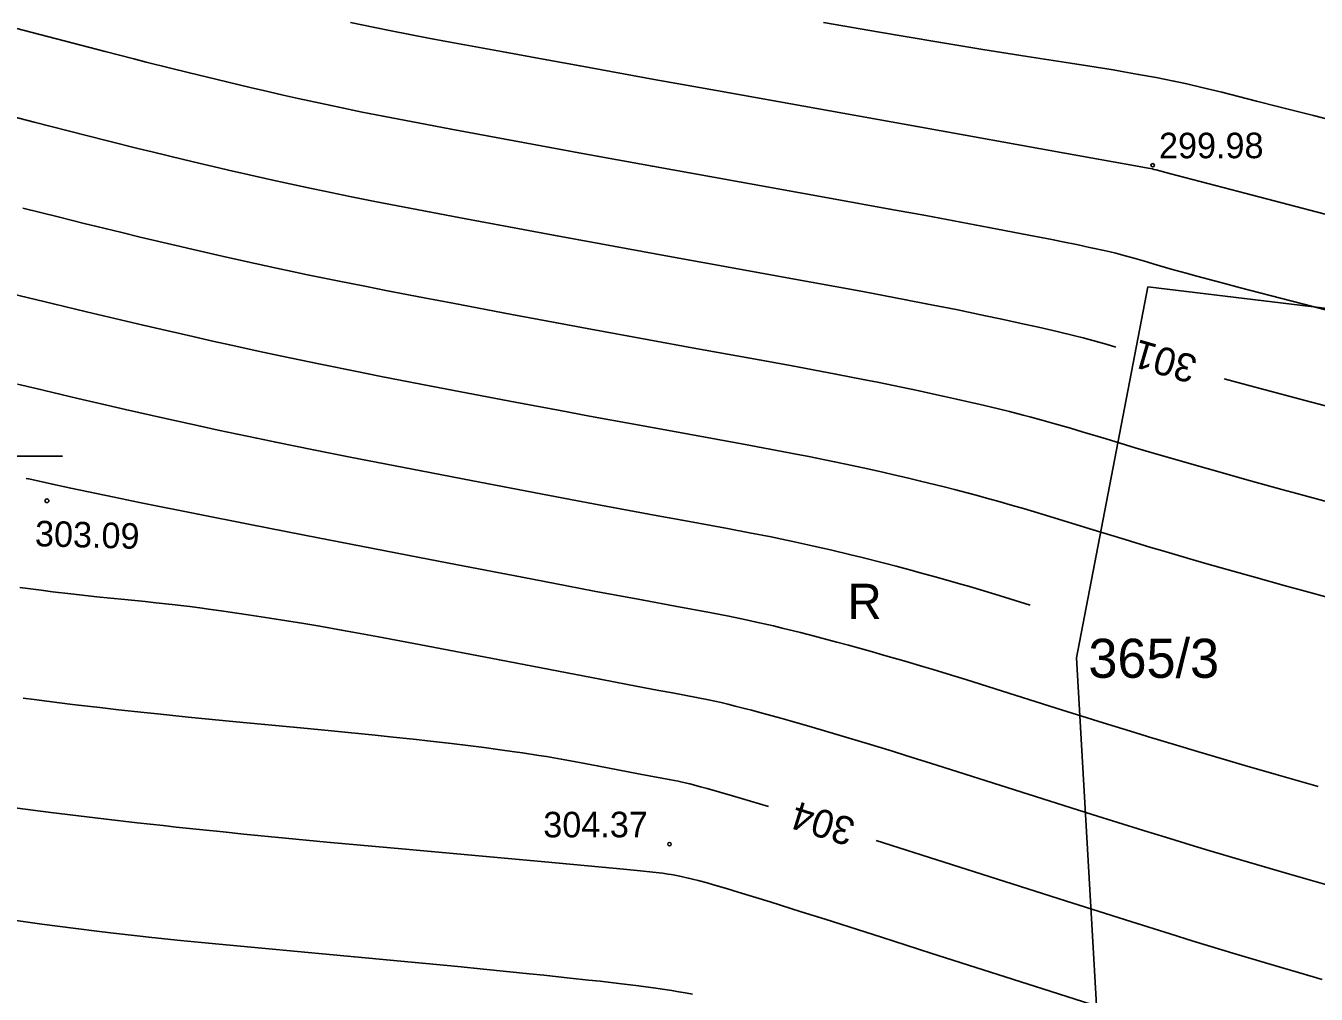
# Model space of a CAD drawing. Extents: x 7477803 to 7478145, y 5500698 to 5500984.
# Drawn here: x 7477901.52 to 7477935.87, y 5500835.67 to 5500861.45 of the extents above; entities that cross this region are included whole.
import ezdxf

# ---------------------------------------------------------------- set-up
doc = ezdxf.new("R2010")
doc.units = 0
for name, color, linetype in [('nr_dzialki', 7, 'Continuous'), ('opis_uzytek', 7, 'Continuous'), ('pkt_wys', 7, 'Continuous'), ('robocza49', 7, 'Continuous'), ('uwagi_projektanci', 7, 'Continuous'), ('warst_ciagla', 7, 'Continuous'), ('warst_opis', 7, 'Continuous'), ('warst_pogrub', 7, 'Continuous'), ('warst_przeryw', 7, 'Continuous')]:
    doc.layers.add(name, color=color, linetype=linetype)

# ---------------------------------------------------------------- blocks, each defined once
blk = doc.blocks.new('801_3')
at = {"layer": 'pkt_wys'}
blk.add_circle((0, 0), 0.045, dxfattribs=at)
blk.add_circle((0, 0), 0.045, dxfattribs=at)
blk = doc.blocks.new('801_5')
at = {"layer": 'pkt_wys'}
blk.add_circle((0, 0), 0.05, dxfattribs=at)
blk.add_circle((0, 0), 0.05, dxfattribs=at)

msp = doc.modelspace()

# ---------------------------------------------------------------- linework, layer by layer
at = {"layer": 'robocza49'}
msp.add_line((7477897.5, 5500850), (7477902.5, 5500850), dxfattribs=at)
at = {"layer": 'uwagi_projektanci'}
msp.add_lwpolyline([(7477973.16, 5500821.11), (7477976.42, 5500829.04), (7477976.7, 5500837.68), (7477975.34, 5500846.14), (7477969.75, 5500849.6), (7477966.4, 5500846.83), (7477944.18, 5500852.96), (7477931.39, 5500854.5), (7477929.49, 5500844.63), (7477930.21, 5500832.13), (7477946.85, 5500819.35), (7477963.16, 5500817.62)], close=True, dxfattribs=at)
at = {"layer": 'warst_ciagla'}
for points in [[(7477900.789, 5500859.139), (7477901.747, 5500858.889), (7477903.136, 5500858.533), (7477903.733, 5500858.383), (7477904.509, 5500858.19), (7477904.889, 5500858.096), (7477905.724, 5500857.895), (7477906.13, 5500857.798), (7477906.662, 5500857.673), (7477906.923, 5500857.612), (7477907.436, 5500857.495), (7477908.1, 5500857.345), (7477908.424, 5500857.274), (7477909.132, 5500857.121), (7477909.476, 5500857.049), (7477910.149, 5500856.911), (7477910.813, 5500856.778), (7477912.162, 5500856.517), (7477913.235, 5500856.314), (7477914.764, 5500856.028), (7477915.57, 5500855.878), (7477916.832, 5500855.646), (7477918.612, 5500855.321), (7477919.544, 5500855.152), (7477922.426, 5500854.631), (7477923.808, 5500854.377), (7477924.95, 5500854.16), (7477925.494, 5500854.055), (7477926.288, 5500853.896), (7477927.068, 5500853.735), (7477927.456, 5500853.653), (7477928.145, 5500853.503), (7477928.484, 5500853.427), (7477928.979, 5500853.313), (7477929.449, 5500853.198), (7477929.672, 5500853.142), (7477930.088, 5500853.03), (7477930.279, 5500852.975), (7477930.54, 5500852.895)], [(7477936.319, 5500846.197), (7477935.483, 5500846.426), (7477935.078, 5500846.537), (7477934.199, 5500846.782), (7477932.962, 5500847.132), (7477932.445, 5500847.282), (7477931.785, 5500847.475), (7477931.468, 5500847.568), (7477930.787, 5500847.773), (7477929.842, 5500848.064), (7477928.664, 5500848.427), (7477928.082, 5500848.6), (7477927.789, 5500848.686), (7477927.393, 5500848.798), (7477927.193, 5500848.853), (7477926.789, 5500848.962), (7477926.244, 5500849.105), (7477925.968, 5500849.176), (7477925.339, 5500849.331), (7477925.02, 5500849.408), (7477924.591, 5500849.508), (7477924.374, 5500849.557), (7477923.938, 5500849.655), (7477923.348, 5500849.782), (7477923.05, 5500849.845), (7477922.371, 5500849.983), (7477922.027, 5500850.05), (7477921.331, 5500850.183), (7477920.624, 5500850.314), (7477919.176, 5500850.578), (7477918.059, 5500850.782), (7477916.53, 5500851.065), (7477915.748, 5500851.211), (7477914.553, 5500851.436), (7477912.919, 5500851.747), (7477912.085, 5500851.907), (7477910.942, 5500852.129), (7477910.34, 5500852.248), (7477909.371, 5500852.444), (7477908.295, 5500852.668), (7477907.707, 5500852.794), (7477906.953, 5500852.958), (7477906.54, 5500853.05), (7477905.856, 5500853.204), (7477904.644, 5500853.483), (7477903.142, 5500853.837), (7477902.26, 5500854.048), (7477900.187, 5500854.55)], [(7477933.421, 5500852.058), (7477934.247, 5500851.836), (7477935.745, 5500851.437), (7477937.058, 5500851.091)], [(7477935.921, 5500841.204), (7477935.177, 5500841.414), (7477934.805, 5500841.52), (7477933.968, 5500841.762), (7477932.713, 5500842.131), (7477932.155, 5500842.298), (7477931.411, 5500842.523), (7477931.04, 5500842.637), (7477930.203, 5500842.896), (7477928.952, 5500843.289), (7477927.324, 5500843.803), (7477926.544, 5500844.046), (7477926.165, 5500844.163), (7477925.672, 5500844.313), (7477925.431, 5500844.385), (7477924.959, 5500844.525), (7477924.352, 5500844.702), (7477924.058, 5500844.786), (7477923.418, 5500844.964), (7477923.11, 5500845.048), (7477922.712, 5500845.155), (7477922.519, 5500845.205), (7477922.142, 5500845.302), (7477921.661, 5500845.42), (7477921.43, 5500845.475), (7477920.933, 5500845.589), (7477920.695, 5500845.64), (7477920.236, 5500845.735), (7477919.78, 5500845.823), (7477918.807, 5500846.003), (7477917.962, 5500846.16), (7477916.656, 5500846.406), (7477915.926, 5500846.545), (7477914.735, 5500846.772), (7477912.968, 5500847.112), (7477912.008, 5500847.297), (7477908.94, 5500847.893), (7477907.456, 5500848.184), (7477906.11, 5500848.451), (7477904.554, 5500848.763), (7477903.877, 5500848.901), (7477902.722, 5500849.141), (7477902.234, 5500849.246), (7477901.603, 5500849.388), (7477901.531, 5500849.405)], [(7477901.457, 5500843.553), (7477901.746, 5500843.515), (7477902.421, 5500843.43), (7477902.77, 5500843.387), (7477903.248, 5500843.331), (7477903.492, 5500843.303), (7477903.991, 5500843.247), (7477904.678, 5500843.172), (7477905.031, 5500843.135), (7477905.847, 5500843.051), (7477907.122, 5500842.927), (7477908.835, 5500842.764), (7477909.66, 5500842.685), (7477910.822, 5500842.568), (7477911.307, 5500842.517), (7477911.925, 5500842.45), (7477912.221, 5500842.417), (7477912.856, 5500842.343), (7477913.728, 5500842.236), (7477914.085, 5500842.189), (7477914.531, 5500842.128), (7477914.741, 5500842.097), (7477915.183, 5500842.031), (7477915.388, 5500841.998), (7477915.77, 5500841.933), (7477916.117, 5500841.87), (7477916.734, 5500841.753), (7477917.873, 5500841.534), (7477918.692, 5500841.38), (7477918.885, 5500841.343), (7477918.994, 5500841.319), (7477919.199, 5500841.27), (7477919.482, 5500841.195), (7477919.661, 5500841.145), (7477920.334, 5500840.952), (7477921.296, 5500840.667)], [(7477924.157, 5500839.765), (7477929.2, 5500838.154), (7477930.967, 5500837.596), (7477931.98, 5500837.28), (7477932.599, 5500837.088), (7477933.738, 5500836.741), (7477934.912, 5500836.39), (7477935.403, 5500836.246), (7477936.026, 5500836.065)]]:
    msp.add_lwpolyline(points, dxfattribs=at)
at = {"layer": 'warst_pogrub'}
for points in [[(7477937.398, 5500856.105), (7477933.804, 5500857.043), (7477931.971, 5500857.521), (7477931.609, 5500857.616), (7477931.553, 5500857.631), (7477931.512, 5500857.642), (7477931.397, 5500857.665), (7477931.159, 5500857.709), (7477929.18, 5500858.065), (7477925.246, 5500858.77), (7477919.912, 5500859.727), (7477918.254, 5500860.025), (7477916.278, 5500860.383), (7477915.392, 5500860.545), (7477914.189, 5500860.765), (7477912.822, 5500861.018), (7477912.239, 5500861.127), (7477911.252, 5500861.316), (7477910.812, 5500861.404), (7477910.167, 5500861.537)], [(7477919.267, 5500835.671), (7477919.132, 5500835.697), (7477918.849, 5500835.748), (7477918.718, 5500835.771), (7477918.469, 5500835.81), (7477918.233, 5500835.844), (7477917.762, 5500835.905), (7477917.378, 5500835.95), (7477916.811, 5500836.015), (7477916.504, 5500836.049), (7477916.015, 5500836.102), (7477915.309, 5500836.177), (7477914.933, 5500836.215), (7477913.704, 5500836.339), (7477913.022, 5500836.406), (7477910.655, 5500836.633), (7477907.807, 5500836.898), (7477906.387, 5500837.03), (7477905.644, 5500837.103), (7477904.88, 5500837.182), (7477904.49, 5500837.224), (7477903.783, 5500837.305), (7477903.419, 5500837.349), (7477902.853, 5500837.42), (7477901.949, 5500837.54), (7477900.957, 5500837.679)]]:
    msp.add_lwpolyline(points, dxfattribs=at)
at = {"layer": 'warst_przeryw'}
for points in [[(7477938.209, 5500853.343), (7477935.746, 5500853.985), (7477933.859, 5500854.477), (7477933.331, 5500854.618), (7477932.696, 5500854.789), (7477932.409, 5500854.868), (7477932.014, 5500854.978), (7477931.557, 5500855.109), (7477931.359, 5500855.168), (7477930.993, 5500855.276), (7477930.787, 5500855.333), (7477930.538, 5500855.397), (7477930.39, 5500855.432), (7477930.224, 5500855.47), (7477929.973, 5500855.525), (7477929.836, 5500855.555), (7477929.535, 5500855.618), (7477929.082, 5500855.711), (7477928.834, 5500855.761), (7477928.22, 5500855.882), (7477927.158, 5500856.086), (7477925.48, 5500856.399), (7477924.527, 5500856.573), (7477922.974, 5500856.855), (7477919.728, 5500857.439), (7477918.205, 5500857.715), (7477916.341, 5500858.054), (7477915.481, 5500858.211), (7477914.28, 5500858.433), (7477912.846, 5500858.7), (7477912.201, 5500858.822), (7477911.033, 5500859.047), (7477910.481, 5500859.157), (7477909.65, 5500859.329), (7477908.776, 5500859.519), (7477908.371, 5500859.61), (7477907.816, 5500859.737), (7477907.531, 5500859.803), (7477906.875, 5500859.959), (7477905.847, 5500860.209), (7477905.374, 5500860.326), (7477904.727, 5500860.489), (7477904.397, 5500860.573), (7477903.638, 5500860.768), (7477901.247, 5500861.391)], [(7477922.756, 5500861.544), (7477924.244, 5500861.285), (7477924.927, 5500861.168), (7477925.876, 5500861.008), (7477927, 5500860.822), (7477927.501, 5500860.742), (7477928.18, 5500860.635), (7477929.334, 5500860.457), (7477929.843, 5500860.377), (7477930.463, 5500860.277), (7477930.748, 5500860.229), (7477931.144, 5500860.16), (7477931.613, 5500860.075), (7477931.822, 5500860.035), (7477932.082, 5500859.983), (7477932.214, 5500859.955), (7477932.43, 5500859.907), (7477932.827, 5500859.813), (7477933.357, 5500859.683), (7477934.285, 5500859.45), (7477934.844, 5500859.308), (7477935.801, 5500859.063), (7477937.298, 5500858.677)], [(7477936.173, 5500848.784), (7477935.353, 5500849.005), (7477934.961, 5500849.112), (7477934.12, 5500849.343), (7477932.967, 5500849.664), (7477932.496, 5500849.798), (7477931.909, 5500849.966), (7477931.632, 5500850.047), (7477931.052, 5500850.219), (7477930.278, 5500850.453), (7477929.646, 5500850.646), (7477929.333, 5500850.739), (7477928.852, 5500850.878), (7477928.6, 5500850.947), (7477928.253, 5500851.04), (7477928.074, 5500851.087), (7477927.705, 5500851.181), (7477927.19, 5500851.307), (7477926.923, 5500851.371), (7477926.299, 5500851.515), (7477925.975, 5500851.587), (7477925.53, 5500851.685), (7477925.302, 5500851.733), (7477924.836, 5500851.832), (7477924.191, 5500851.963), (7477923.86, 5500852.03), (7477923.089, 5500852.18), (7477921.879, 5500852.407), (7477921.046, 5500852.559), (7477919.36, 5500852.865), (7477918.108, 5500853.093), (7477916.467, 5500853.395), (7477915.659, 5500853.545), (7477914.462, 5500853.769), (7477912.895, 5500854.065), (7477912.124, 5500854.212), (7477911.104, 5500854.409), (7477910.594, 5500854.509), (7477909.818, 5500854.664), (7477909.022, 5500854.827), (7477908.615, 5500854.913), (7477908.199, 5500855.002), (7477907.631, 5500855.126), (7477907.342, 5500855.19), (7477906.752, 5500855.322), (7477905.943, 5500855.508), (7477905.529, 5500855.604), (7477904.572, 5500855.83), (7477904.082, 5500855.949), (7477903.415, 5500856.111), (7477903.076, 5500856.194), (7477902.386, 5500856.365), (7477901.444, 5500856.602)], [(7477901.306, 5500851.914), (7477901.802, 5500851.794), (7477902.907, 5500851.532), (7477903.453, 5500851.405), (7477904.174, 5500851.238), (7477904.532, 5500851.157), (7477905.243, 5500850.998), (7477906.178, 5500850.791), (7477906.641, 5500850.691), (7477907.671, 5500850.473), (7477908.179, 5500850.368), (7477909.181, 5500850.164), (7477910.162, 5500849.969), (7477912.047, 5500849.602), (7477913.381, 5500849.346), (7477915.049, 5500849.027), (7477915.837, 5500848.878), (7477916.959, 5500848.667), (7477918.345, 5500848.409), (7477918.992, 5500848.29), (7477920.202, 5500848.068), (7477920.783, 5500847.959), (7477921.361, 5500847.845), (7477921.652, 5500847.786), (7477921.944, 5500847.724), (7477922.339, 5500847.638), (7477922.537, 5500847.594), (7477922.939, 5500847.502), (7477923.481, 5500847.373), (7477923.755, 5500847.306), (7477924.379, 5500847.148), (7477924.694, 5500847.066), (7477925.119, 5500846.952), (7477925.334, 5500846.894), (7477925.766, 5500846.774), (7477926.349, 5500846.608), (7477926.643, 5500846.523), (7477927.313, 5500846.323), (7477928.257, 5500846.033)], [(7477901.369, 5500846.501), (7477901.934, 5500846.424), (7477902.238, 5500846.385), (7477902.721, 5500846.328), (7477903.414, 5500846.252), (7477903.782, 5500846.215), (7477904.164, 5500846.177), (7477904.701, 5500846.124), (7477904.983, 5500846.095), (7477905.424, 5500846.046), (7477905.654, 5500846.02), (7477905.89, 5500845.991), (7477906.216, 5500845.949), (7477906.383, 5500845.927), (7477906.726, 5500845.88), (7477907.201, 5500845.811), (7477907.447, 5500845.775), (7477908.018, 5500845.686), (7477908.925, 5500845.538), (7477909.347, 5500845.466), (7477909.928, 5500845.364), (7477910.226, 5500845.311), (7477910.916, 5500845.185), (7477911.993, 5500844.983), (7477914.133, 5500844.571), (7477916.812, 5500844.056), (7477917.537, 5500843.918), (7477918.374, 5500843.761), (7477918.737, 5500843.694), (7477919.378, 5500843.574), (7477919.692, 5500843.51), (7477920.03, 5500843.435), (7477920.214, 5500843.392), (7477920.41, 5500843.344), (7477920.692, 5500843.272), (7477920.843, 5500843.233), (7477921.16, 5500843.148), (7477921.621, 5500843.021), (7477921.867, 5500842.951), (7477922.458, 5500842.781), (7477923.444, 5500842.488), (7477923.921, 5500842.344), (7477924.593, 5500842.138), (7477924.945, 5500842.029), (7477925.775, 5500841.769), (7477929.91, 5500840.458), (7477931.274, 5500840.033), (7477931.864, 5500839.851), (7477932.636, 5500839.616), (7477933.015, 5500839.502), (7477933.853, 5500839.251), (7477935.068, 5500838.895), (7477935.592, 5500838.744), (7477936.276, 5500838.55)], [(7477930.093, 5500835.334), (7477928.594, 5500835.812), (7477925.61, 5500836.769), (7477924.299, 5500837.189), (7477922.802, 5500837.666), (7477922.162, 5500837.868), (7477921.337, 5500838.128), (7477920.489, 5500838.39), (7477920.174, 5500838.486), (7477919.827, 5500838.588), (7477919.661, 5500838.634), (7477919.421, 5500838.697), (7477919.269, 5500838.734), (7477919.087, 5500838.777), (7477919.004, 5500838.796), (7477918.889, 5500838.821), (7477918.756, 5500838.848), (7477918.698, 5500838.858), (7477918.619, 5500838.871), (7477918.473, 5500838.891), (7477918.214, 5500838.92), (7477917.89, 5500838.955), (7477917.243, 5500839.017), (7477915.243, 5500839.202), (7477911.63, 5500839.532), (7477909.54, 5500839.724), (7477908.437, 5500839.828), (7477907.329, 5500839.936), (7477906.78, 5500839.991), (7477906.238, 5500840.047), (7477905.529, 5500840.122), (7477905.179, 5500840.16), (7477904.49, 5500840.236), (7477903.592, 5500840.34), (7477903.153, 5500840.393), (7477902.187, 5500840.512), (7477901.715, 5500840.573), (7477901.099, 5500840.655)]]:
    msp.add_lwpolyline(points, dxfattribs=at)

# ---------------------------------------------------------------- block references
at = {"layer": 'pkt_wys', "rotation": 0.0626175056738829}
for name, p in [('801_3', (7477931.519, 5500857.741)), ('801_5', (7477902.088, 5500848.809)), ('801_3', (7477918.658, 5500839.667))]:
    msp.add_blockref(name, p, dxfattribs=at)

# ---------------------------------------------------------------- texts
at = {"layer": 'nr_dzialki'}
msp.add_text('365/3', height=1.04, dxfattribs=at).set_placement((7477929.808, 5500844.095))
at = {"layer": 'opis_uzytek'}
msp.add_text('R', height=0.94, dxfattribs=at).set_placement((7477923.398, 5500845.659))
at = {"layer": 'pkt_wys'}
for s, rotation, p in [('299.98', 0.0626, (7477931.688, 5500857.925)), ('303.09', 358.4641, (7477901.762, 5500847.6)), ('304.37', 0.0626, (7477915.3, 5500839.847))]:
    msp.add_text(s, height=0.68, rotation=rotation, dxfattribs=at).set_placement(p)
at = {"layer": 'warst_opis'}
for s, rotation, p in [('301', 163.7975, (7477932.754, 5500852.642)), ('304', 162.5082, (7477923.651, 5500840.318))]:
    msp.add_text(s, height=0.75, rotation=rotation, dxfattribs=at).set_placement(p)

doc.saveas('drawing.dxf')
